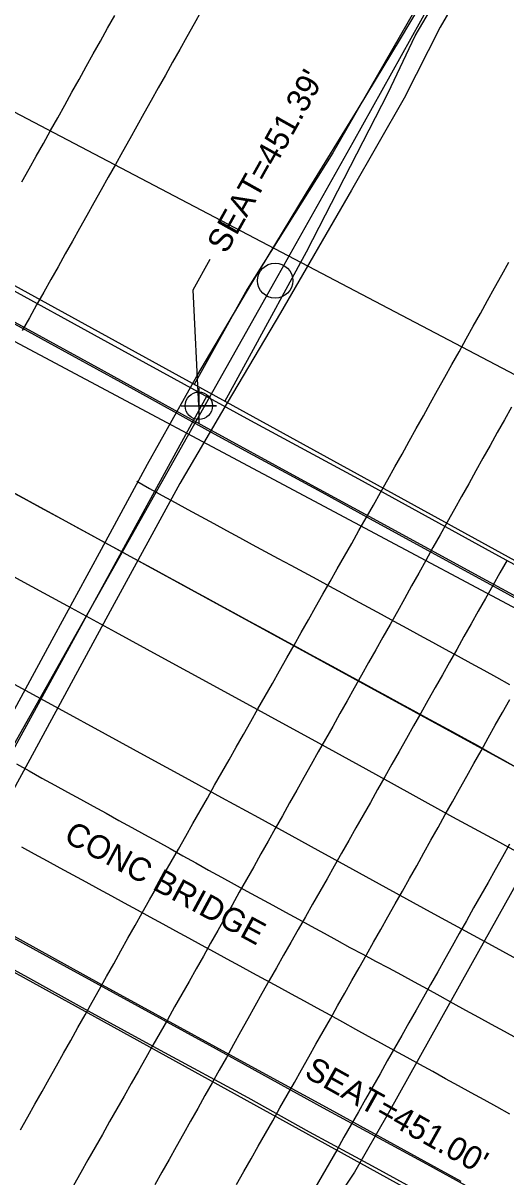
# Model space of a CAD drawing. Extents: x 2074109 to 2077820, y 741079 to 746031.
# Drawn here: x 2075532.2 to 2075614.7, y 743274.4 to 743471.4 of the extents above; entities that cross this region are included whole.
import ezdxf

# ---------------------------------------------------------------- set-up
doc = ezdxf.new("R2010")
doc.units = 0
for name, color, linetype in [('Exist Guardrail', 7, 'Continuous'), ('Exist Horizontal Alignment', 7, 'Continuous'), ('Exist Horizontal Alignment Point', 7, 'Continuous'), ('Exist Roads EOP', 7, 'Continuous'), ('Exist Roads EOP Other', 7, 'Continuous'), ('Exist Roads EOT', 7, 'Continuous'), ('Exist Structure Major Bridge Seam', 7, 'Continuous'), ('Exist Structure Major Bridge Seat Cogo Point CELL', 7, 'Continuous'), ('Exist Structure Major Bridge Seat Leader', 7, 'Continuous'), ('Exist Structure Major Bridge Seat Top Elevation', 7, 'Continuous'), ('Exist Structure Major Deck Tunnel Box Culvert', 7, 'Continuous'), ('Exist Structure Major Deck Tunnel Box Culvert Text', 7, 'Continuous'), ('Exist Utilities Telephone UG Conduit SUE LOS B', 7, 'Continuous'), ('Exist Utilities Water UG Line SUE LOS B', 7, 'Continuous')]:
    doc.layers.add(name, color=color, linetype=linetype)

msp = doc.modelspace()

# ---------------------------------------------------------------- linework, layer by layer
at = {"layer": 'Exist Guardrail'}
msp.add_line((2075608.81, 743490.52), (2075585.08, 743449.24), dxfattribs=at)
for points in [[(2075566.68, 743406.83), (2075570.84, 743414.46), (2075580.6, 743432.36), (2075594.55, 743459.51), (2075599.18, 743469.22), (2075611.18, 743489.67), (2075614, 743495.32), (2075613.66, 743496.05), (2075612.79, 743496.46), (2075612.4, 743496.03), (2075608.81, 743490.52)], [(2075585.08, 743449.24), (2075570.45, 743425.99), (2075561.4, 743409.73)]]:
    msp.add_lwpolyline(points, dxfattribs=at)
at = {"layer": 'Exist Horizontal Alignment'}
for p, q in [((2074769.18, 743807.11), (2075920.37, 743178.35)), ((2074886.11, 742205.34), (2075575.25, 743427.42))]:
    msp.add_line(p, q, dxfattribs=at)
msp.add_arc((2065746.77, 748969.72), 11283.45, 330.581241, 339.398504, dxfattribs=at)
at = {"layer": 'Exist Horizontal Alignment Point'}
msp.add_circle((2075575.25, 743427.42), 3, dxfattribs=at)
at = {"layer": 'Exist Roads EOP'}
for points in [[(2075629.48, 743509.98), (2075612.24, 743485.93), (2075603.42, 743470.69), (2075597.29, 743458.57), (2075588.31, 743442.87), (2075576.16, 743421.96), (2075567.04, 743406.6), (2075558.96, 743392.83), (2075547.09, 743371), (2075533.33, 743345.7), (2075516.25, 743314.4), (2075505.25, 743295.15), (2075496.54, 743281.14), (2075486.37, 743264.69)], [(2075486.59, 743271.21), (2075492.62, 743282.79), (2075498.41, 743293.66), (2075503.35, 743303.11), (2075507.27, 743311), (2075512.55, 743321.1), (2075520.08, 743334.84), (2075528.48, 743350.15), (2075537.18, 743366.11), (2075545.57, 743381.57), (2075553.44, 743396.13), (2075561.87, 743411.12), (2075571.26, 743427.01), (2075580.6, 743442.44), (2075589.42, 743456.78), (2075596.67, 743468.69), (2075601.96, 743477.67), (2075605.92, 743484.73), (2075608.84, 743490.35), (2075611.2, 743495.58), (2075613.21, 743500.83), (2075614.86, 743505.48)], [(2075621.09, 743327.41), (2075613, 743331.84), (2075605.63, 743335.87), (2075598.33, 743339.89), (2075590.79, 743344.03), (2075582.71, 743348.46), (2075574.05, 743353.19), (2075564.79, 743358.25), (2075555.8, 743363.16), (2075547.98, 743367.41), (2075540.47, 743371.5), (2075532.37, 743375.92), (2075523.96, 743380.52)], [(2075529.4, 743359.25), (2075538.28, 743354.38), (2075546.23, 743350.05), (2075553.38, 743346.16), (2075559.87, 743342.61), (2075566.08, 743339.21), (2075572.4, 743335.76), (2075578.12, 743332.63), (2075582.53, 743330.22), (2075587.32, 743327.59), (2075594.18, 743323.83), (2075602.35, 743319.37), (2075611.07, 743314.6), (2075619.49, 743310)], [(2075623.56, 743337.14), (2075608.64, 743310.49), (2075594.58, 743285.23), (2075588.82, 743275.24), (2075585.74, 743270.66), (2075574.13, 743250.39), (2075561.59, 743227.72), (2075550.55, 743206.86), (2075542.79, 743191.97), (2075536.69, 743180.08), (2075530.38, 743166.92), (2075524.95, 743155.11), (2075523.03, 743151.26), (2075521.7, 743149.07), (2075521.03, 743147.94), (2075519.6, 743146.97), (2075518.85, 743146.27), (2075518.17, 743146.62), (2075517.61, 743146.64), (2075516.93, 743144.83), (2075514.92, 743139.3), (2075512.25, 743130.75), (2075509.54, 743120.91)]]:
    msp.add_lwpolyline(points, dxfattribs=at)
at = {"layer": 'Exist Roads EOP Other'}
for points in [[(2075446.9, 743466.16), (2075450.85, 743469.27), (2075458.75, 743464.97), (2075480.04, 743453.4), (2075506.88, 743438.69), (2075527.73, 743427.3), (2075546.63, 743416.96), (2075571.03, 743403.56), (2075589.49, 743393.59), (2075613.42, 743380.47), (2075627.96, 743372.52)], [(2075619.2, 743371.98), (2075608.74, 743377.69), (2075594.58, 743385.42), (2075579.57, 743393.56), (2075563.15, 743402.56), (2075545.57, 743412.2), (2075528.46, 743421.58), (2075513.1, 743429.9), (2075496.22, 743439.15), (2075484.66, 743445.5), (2075471.98, 743452.44), (2075457.75, 743460.19), (2075446.9, 743466.16)], [(2075366.87, 743399.63), (2075391.52, 743386.11), (2075399.31, 743381.63), (2075400.42, 743380.9), (2075400.42, 743380.9), (2075417.05, 743371.88), (2075424.34, 743367.81), (2075437.43, 743360.73), (2075449.67, 743354.08), (2075462.75, 743347.04), (2075479.55, 743337.75), (2075493.27, 743330.26), (2075511.78, 743320.13), (2075532.97, 743308.52), (2075543.32, 743302.78), (2075555.58, 743296.07), (2075570.56, 743287.96), (2075581.08, 743282.13), (2075591.83, 743276.3), (2075602.54, 743270.44)], [(2075618.54, 743267.07), (2075601.14, 743276.62), (2075583.53, 743286.17), (2075564.08, 743296.86), (2075539.72, 743310.19), (2075523.4, 743319.09), (2075507.55, 743327.8), (2075492.26, 743336.14), (2075475.25, 743345.43), (2075460.95, 743353.21), (2075441.94, 743363.59), (2075425.56, 743372.59), (2075411.83, 743380.02), (2075402.45, 743385.14)]]:
    msp.add_lwpolyline(points, dxfattribs=at)
at = {"layer": 'Exist Roads EOT'}
for points in [[(2075532, 743444.33), (2075533.23, 743446.51), (2075534.45, 743448.69), (2075535.67, 743450.87), (2075536.9, 743453.05), (2075538.12, 743455.23), (2075539.33, 743457.42), (2075540.54, 743459.6), (2075541.75, 743461.79), (2075542.97, 743463.97), (2075544.19, 743466.16), (2075545.41, 743468.34), (2075546.63, 743470.52), (2075547.85, 743472.7)], [(2075562.61, 743473.44), (2075561.39, 743471.25), (2075560.17, 743469.07), (2075558.95, 743466.89), (2075557.73, 743464.71), (2075556.51, 743462.53), (2075555.28, 743460.35), (2075554.06, 743458.17), (2075552.84, 743455.99), (2075551.62, 743453.81), (2075550.4, 743451.63), (2075549.17, 743449.45), (2075547.95, 743447.27), (2075546.73, 743445.09), (2075545.51, 743442.91), (2075544.29, 743440.73), (2075543.06, 743438.54), (2075541.84, 743436.36), (2075540.62, 743434.18), (2075539.4, 743432), (2075538.18, 743429.82), (2075536.95, 743427.64), (2075535.73, 743425.46), (2075534.5, 743423.29), (2075533.27, 743421.11), (2075532.04, 743418.93)], [(2075531.77, 743282.48), (2075532.99, 743284.66), (2075534.22, 743286.84), (2075535.44, 743289.02), (2075536.66, 743291.2), (2075537.88, 743293.38), (2075539.11, 743295.56), (2075540.33, 743297.74), (2075541.55, 743299.92), (2075542.77, 743302.1), (2075544, 743304.28), (2075545.22, 743306.46), (2075546.44, 743308.64), (2075547.67, 743310.82), (2075548.89, 743313), (2075550.11, 743315.18), (2075551.33, 743317.36), (2075552.56, 743319.54), (2075553.8, 743321.71), (2075555.03, 743323.89), (2075556.26, 743326.06), (2075557.5, 743328.23), (2075558.73, 743330.41), (2075559.97, 743332.58), (2075561.2, 743334.76), (2075562.43, 743336.93), (2075563.67, 743339.11), (2075564.9, 743341.28), (2075566.13, 743343.45), (2075567.37, 743345.63), (2075568.6, 743347.8), (2075569.83, 743349.98), (2075571.07, 743352.15), (2075572.3, 743354.32), (2075573.53, 743356.5), (2075574.77, 743358.67), (2075576, 743360.85), (2075577.23, 743363.02), (2075578.47, 743365.2), (2075579.7, 743367.37), (2075580.93, 743369.54), (2075582.17, 743371.72), (2075583.4, 743373.89), (2075584.63, 743376.07), (2075585.87, 743378.24), (2075587.1, 743380.42), (2075588.33, 743382.59), (2075589.57, 743384.76), (2075590.8, 743386.94), (2075592.03, 743389.11), (2075593.27, 743391.29), (2075594.49, 743393.47), (2075595.71, 743395.65), (2075596.92, 743397.83), (2075598.14, 743400.02), (2075599.36, 743402.2), (2075600.57, 743404.38), (2075601.79, 743406.57), (2075603.01, 743408.75), (2075604.22, 743410.94), (2075605.44, 743413.12), (2075606.66, 743415.3), (2075607.87, 743417.49), (2075609.09, 743419.67), (2075610.31, 743421.85), (2075611.52, 743424.04), (2075612.74, 743426.22), (2075613.96, 743428.4), (2075615.17, 743430.59)], [(2075615.62, 743405.86), (2075614.4, 743403.68), (2075613.18, 743401.5), (2075611.96, 743399.32), (2075610.75, 743397.14), (2075609.53, 743394.95), (2075608.31, 743392.77), (2075607.09, 743390.59), (2075605.87, 743388.41), (2075604.65, 743386.22), (2075603.43, 743384.04), (2075602.21, 743381.86), (2075600.99, 743379.68), (2075599.78, 743377.49), (2075598.56, 743375.31), (2075597.35, 743373.13), (2075596.13, 743370.94), (2075594.9, 743368.76), (2075593.67, 743366.59), (2075592.45, 743364.41), (2075591.22, 743362.23), (2075589.99, 743360.06), (2075588.76, 743357.88), (2075587.53, 743355.7), (2075586.31, 743353.52), (2075585.08, 743351.35), (2075583.85, 743349.17), (2075582.62, 743346.99), (2075581.4, 743344.81), (2075580.17, 743342.63), (2075578.95, 743340.45), (2075577.72, 743338.28), (2075576.5, 743336.1), (2075575.27, 743333.92), (2075574.04, 743331.74), (2075572.81, 743329.56), (2075571.59, 743327.39), (2075570.36, 743325.21), (2075569.13, 743323.03), (2075567.91, 743320.85), (2075566.68, 743318.68), (2075565.45, 743316.5), (2075564.22, 743314.32), (2075563, 743312.14), (2075561.77, 743309.96), (2075560.54, 743307.79), (2075559.31, 743305.61), (2075558.08, 743303.44), (2075556.85, 743301.26), (2075555.62, 743299.09), (2075554.38, 743296.91), (2075553.15, 743294.74), (2075551.92, 743292.56), (2075550.68, 743290.39), (2075549.45, 743288.21), (2075548.22, 743286.04), (2075546.98, 743283.87), (2075545.75, 743281.69), (2075544.52, 743279.52), (2075543.28, 743277.34), (2075542.05, 743275.17), (2075540.82, 743272.99)], [(2075551.6, 743393.18), (2075553.79, 743391.97), (2075555.97, 743390.75), (2075558.17, 743389.55), (2075560.36, 743388.36), (2075562.56, 743387.17), (2075564.76, 743385.98), (2075566.96, 743384.79), (2075569.16, 743383.6), (2075571.35, 743382.41), (2075573.55, 743381.22), (2075575.75, 743380.03), (2075577.95, 743378.84), (2075580.15, 743377.65), (2075582.35, 743376.46), (2075584.54, 743375.27), (2075586.74, 743374.07), (2075588.94, 743372.88), (2075591.14, 743371.69), (2075593.34, 743370.5), (2075595.53, 743369.3), (2075597.72, 743368.11), (2075599.92, 743366.91), (2075602.11, 743365.71), (2075604.31, 743364.51), (2075606.5, 743363.31), (2075608.7, 743362.12), (2075610.89, 743360.92), (2075613.08, 743359.72), (2075615.28, 743358.52)], [(2075530.69, 743391.16), (2075532.88, 743389.96), (2075535.08, 743388.76), (2075537.27, 743387.56), (2075539.47, 743386.37), (2075541.66, 743385.17), (2075543.85, 743383.97), (2075546.05, 743382.78), (2075548.25, 743381.58), (2075550.44, 743380.39), (2075552.64, 743379.2), (2075554.84, 743378), (2075557.03, 743376.81), (2075559.23, 743375.61), (2075561.43, 743374.42), (2075563.62, 743373.22), (2075565.82, 743372.03), (2075568.01, 743370.84), (2075570.21, 743369.64), (2075572.41, 743368.45), (2075574.6, 743367.25), (2075576.8, 743366.06), (2075579, 743364.87), (2075581.2, 743363.68), (2075583.4, 743362.49), (2075585.59, 743361.3), (2075587.79, 743360.11), (2075589.99, 743358.91), (2075592.18, 743357.71), (2075594.37, 743356.52), (2075596.57, 743355.32), (2075598.76, 743354.12), (2075600.96, 743352.92), (2075603.15, 743351.73), (2075605.35, 743350.53), (2075607.54, 743349.33), (2075609.73, 743348.12), (2075611.91, 743346.9), (2075614.09, 743345.68), (2075616.28, 743344.46)], [(2075614.89, 743379.72), (2075613.65, 743377.55), (2075612.41, 743375.38), (2075611.17, 743373.2), (2075609.95, 743371.03), (2075608.72, 743368.85), (2075607.5, 743366.67), (2075606.27, 743364.49), (2075605.04, 743362.31), (2075603.81, 743360.14), (2075602.58, 743357.96), (2075601.35, 743355.78), (2075600.12, 743353.61), (2075598.89, 743351.43), (2075597.66, 743349.26), (2075596.43, 743347.08), (2075595.2, 743344.9), (2075593.97, 743342.73), (2075592.74, 743340.55), (2075591.51, 743338.37), (2075590.28, 743336.2), (2075589.05, 743334.03), (2075587.81, 743331.85), (2075586.58, 743329.68), (2075585.34, 743327.5), (2075584.11, 743325.33), (2075582.88, 743323.16), (2075581.64, 743320.98), (2075580.41, 743318.81), (2075579.17, 743316.64), (2075577.94, 743314.46), (2075576.7, 743312.29), (2075575.47, 743310.11), (2075574.23, 743307.94), (2075573, 743305.77), (2075571.77, 743303.59), (2075570.56, 743301.4), (2075569.35, 743299.21), (2075568.15, 743297.03), (2075566.93, 743294.84), (2075565.71, 743292.66), (2075564.48, 743290.48), (2075563.25, 743288.31), (2075562.03, 743286.13), (2075560.8, 743283.95), (2075559.58, 743281.77), (2075558.35, 743279.59), (2075557.12, 743277.41), (2075555.9, 743275.23), (2075554.67, 743273.06)], [(2075568.66, 743273.16), (2075569.89, 743275.34), (2075571.13, 743277.51), (2075572.36, 743279.69), (2075573.6, 743281.86), (2075574.83, 743284.03), (2075576.06, 743286.21), (2075577.3, 743288.38), (2075578.53, 743290.56), (2075579.76, 743292.73), (2075580.99, 743294.91), (2075582.22, 743297.08), (2075583.45, 743299.26), (2075584.68, 743301.44), (2075585.91, 743303.61), (2075587.14, 743305.79), (2075588.37, 743307.97), (2075589.6, 743310.14), (2075590.83, 743312.32), (2075592.06, 743314.5), (2075593.29, 743316.67), (2075594.52, 743318.85), (2075595.75, 743321.03), (2075596.98, 743323.2), (2075598.21, 743325.38), (2075599.43, 743327.56), (2075600.65, 743329.74), (2075601.87, 743331.92), (2075603.1, 743334.1), (2075604.32, 743336.28), (2075605.54, 743338.46), (2075606.76, 743340.64), (2075607.98, 743342.83), (2075609.2, 743345.01), (2075610.42, 743347.19), (2075611.64, 743349.37), (2075612.86, 743351.55), (2075614.08, 743353.73), (2075615.31, 743355.91)], [(2075531.04, 743344.94), (2075533.23, 743343.73), (2075535.42, 743342.53), (2075537.61, 743341.32), (2075539.8, 743340.11), (2075541.99, 743338.91), (2075544.18, 743337.7), (2075546.37, 743336.5), (2075548.56, 743335.29), (2075550.75, 743334.09), (2075552.94, 743332.88), (2075555.13, 743331.68), (2075557.32, 743330.47), (2075559.5, 743329.25), (2075561.68, 743328.03), (2075563.87, 743326.81), (2075566.06, 743325.61), (2075568.25, 743324.41), (2075570.44, 743323.21), (2075572.64, 743322.01), (2075574.83, 743320.81), (2075577.03, 743319.62), (2075579.22, 743318.42), (2075581.41, 743317.22), (2075583.61, 743316.02), (2075585.8, 743314.82), (2075588, 743313.62), (2075590.2, 743312.45), (2075592.41, 743311.28), (2075594.62, 743310.11), (2075596.83, 743308.93), (2075599.02, 743307.73), (2075601.21, 743306.53), (2075603.4, 743305.32), (2075605.59, 743304.12), (2075607.78, 743302.92), (2075609.98, 743301.71), (2075612.17, 743300.51), (2075614.36, 743299.31), (2075616.55, 743298.1)], [(2075615.32, 743285.17), (2075613.13, 743286.38), (2075610.94, 743287.58), (2075608.75, 743288.79), (2075606.55, 743289.99), (2075604.36, 743291.2), (2075602.17, 743292.4), (2075599.98, 743293.61), (2075597.79, 743294.81), (2075595.6, 743296.01), (2075593.41, 743297.22), (2075591.22, 743298.42), (2075589.02, 743299.62), (2075586.83, 743300.82), (2075584.64, 743302.02), (2075582.44, 743303.21), (2075580.25, 743304.41), (2075578.05, 743305.6), (2075575.86, 743306.8), (2075573.66, 743308), (2075571.46, 743309.19), (2075569.27, 743310.39), (2075567.07, 743311.58), (2075564.88, 743312.78), (2075562.68, 743313.97), (2075560.49, 743315.17), (2075558.29, 743316.37), (2075556.1, 743317.57), (2075553.91, 743318.77), (2075551.72, 743319.97), (2075549.52, 743321.17), (2075547.33, 743322.37), (2075545.13, 743323.57), (2075542.94, 743324.76), (2075540.74, 743325.96), (2075538.55, 743327.16), (2075536.36, 743328.36), (2075534.16, 743329.55), (2075531.97, 743330.75)], [(2075615.28, 743331.24), (2075614.06, 743329.06), (2075612.84, 743326.88), (2075611.61, 743324.7), (2075610.39, 743322.52), (2075609.16, 743320.34), (2075607.94, 743318.16), (2075606.71, 743315.99), (2075605.49, 743313.81), (2075604.26, 743311.63), (2075603.03, 743309.45), (2075601.8, 743307.28), (2075600.57, 743305.1), (2075599.34, 743302.92), (2075598.11, 743300.75), (2075596.88, 743298.57), (2075595.64, 743296.4), (2075594.41, 743294.22), (2075593.18, 743292.05), (2075591.95, 743289.87), (2075590.71, 743287.7), (2075589.47, 743285.53), (2075588.23, 743283.36), (2075587, 743281.19), (2075585.76, 743279.01), (2075584.52, 743276.84), (2075583.28, 743274.67), (2075582.04, 743272.5)]]:
    msp.add_lwpolyline(points, dxfattribs=at)
at = {"layer": 'Exist Structure Major Bridge Seam'}
msp.add_line((2075563.57, 743407.75), (2075514.69, 743318.53), dxfattribs=at)
at = {"layer": 'Exist Structure Major Bridge Seat Cogo Point CELL'}
msp.add_lwpolyline([(2075559.22, 743406.08), (2075565.22, 743406.08), (2075562.22, 743406.08), (2075562.22, 743409.08), (2075562.22, 743403.08)], dxfattribs=at)
msp.add_circle((2075562.22, 743406.08), 2.34, dxfattribs=at)
at = {"layer": 'Exist Structure Major Bridge Seat Leader'}
msp.add_lwpolyline([(2075562.22, 743406.08), (2075561.23, 743425.87), (2075564.16, 743431.11)], dxfattribs=at)
at = {"layer": 'Exist Structure Major Deck Tunnel Box Culvert'}
for p, q in [((2075449.46, 743471.22), (2075674.49, 743347.61)), ((2075625.56, 743257.09), (2075399.85, 743381.42))]:
    msp.add_line(p, q, dxfattribs=at)
for points in [[(2075522.18, 743424.71), (2075536.42, 743416.95), (2075548.87, 743410.1), (2075554.75, 743406.87), (2075564.23, 743401.65), (2075571.44, 743397.71), (2075583.21, 743391.3), (2075591.49, 743386.79), (2075601.28, 743381.44), (2075613.19, 743374.96), (2075627.29, 743367.22)], [(2075607.03, 743273.66), (2075584.65, 743285.92), (2075571.79, 743292.92), (2075545.13, 743307.48), (2075524.18, 743319.04)]]:
    msp.add_lwpolyline(points, dxfattribs=at)
at = {"layer": 'Exist Utilities Telephone UG Conduit SUE LOS B'}
msp.add_lwpolyline([(2074852.23, 743796.93), (2074858.98, 743788.14), (2074871.16, 743780.09), (2074884.61, 743773.35), (2074910.14, 743759.3), (2074929.12, 743745.39), (2074958.42, 743728.87), (2074997.61, 743706.69), (2075052.29, 743677.02), (2075084.82, 743660.77), (2075107.9, 743645.87), (2075165.73, 743622.21), (2075198.81, 743604.97), (2075246.84, 743581.99), (2075289.9, 743561.06), (2075322.06, 743548.08), (2075339.73, 743539.52), (2075355.79, 743530.19), (2075360.13, 743528.64), (2075373.71, 743515.02), (2075393.05, 743495.87), (2075443.09, 743463.69), (2075672.89, 743341.39)], dxfattribs=at)
at = {"layer": 'Exist Utilities Water UG Line SUE LOS B'}
msp.add_lwpolyline([(2074661.41, 743894.07), (2074669.03, 743889.86), (2074695.78, 743877.33), (2074733.5, 743856.32), (2074766.19, 743837.03), (2074806.52, 743814.12), (2074828.36, 743801.4), (2074869.77, 743778.77), (2075138.71, 743653.82), (2075174.59, 743638.37), (2075261.38, 743603.22), (2075296.53, 743589.33), (2075345.56, 743568.62), (2075373.37, 743552.36), (2075399.34, 743536.02), (2075447.19, 743500.05), (2075713.36, 743360.43), (2075744.72, 743342.27), (2075764.85, 743330.17), (2075782.75, 743317.7), (2075822.78, 743289.56)], dxfattribs=at)

# ---------------------------------------------------------------- texts
at = {"layer": 'Exist Structure Major Bridge Seat Top Elevation'}
for s, rotation, p in [("SEAT=451.39'", 60.742, (2075566.88, 743431.87)), ("SEAT=451.00'", 330.742, (2075580.04, 743291.64))]:
    msp.add_text(s, height=4, rotation=rotation, dxfattribs=at).set_placement(p)
at = {"layer": 'Exist Structure Major Deck Tunnel Box Culvert Text'}
msp.add_text('CONC BRIDGE', height=4, rotation=331.6254, dxfattribs=at).set_placement((2075538.94, 743331.83))

doc.saveas('drawing.dxf')
